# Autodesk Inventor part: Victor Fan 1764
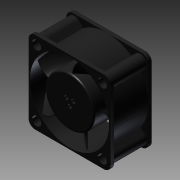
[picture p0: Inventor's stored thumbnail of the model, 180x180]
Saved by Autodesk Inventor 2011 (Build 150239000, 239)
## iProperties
Shininess: 64.0
Length Units: 11272
Angle Units: 11279
Time Units: 11290
Mass Units: 11286
Length Display Precision: 3
Angle Display Precision: 2
Compacted: True
Part Number: Victor Fan 1764
Document SubType Name: Modeling
Created: 2005-12
Designer: Owner
Material: ABS Plastic
Density: 1 g/cm^3
Density: 0.0
Volumn: 0.0
Area: 0.0
PropertySet Name: Model Information
Control State: 0
Master: False
Checked Out: False
Author: Owner
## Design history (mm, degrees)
sketch "Sketch1"
  geometry: L1 (-19.939, 19.939)-(19.939, 19.939); L2 (19.939, 19.939)-(19.939, -19.939); L3 (19.939, -19.939)-(-19.939, -19.939); L4 (-19.939, -19.939)-(-19.939, 19.939); L5 (0, 0)-(0, 19.939); L6 (0, 0)-(0, -19.939); L7 (0, 0)-(19.939, 0); L8 (0, 0)-(-19.939, 0)
  constraints: 16 end point, 4 midpoint, 3 equal length, 3 perpendicular, 2 parallel, 1 horizontal, 1 other
  dimensions: "d0" = 39.878 distance of L1.start L1.end
extrude "Extrusion1" new body sketch "Sketch1" stored distance "d1" = 20.066; taper "d2" = 0 deg
sketch "Sketch2"
  geometry: L1 (19.939, 10.033)-(-19.939, 10.033) reference; L2 (19.939, 10.033)-(19.939, -10.033) reference; L3 (-19.939, -10.033)-(19.939, -10.033) reference; L4 (19.939, 8.331)-(32.639, 8.331); L5 (32.639, 8.331)-(32.639, -8.331); L6 (32.639, -8.331)-(19.939, -8.331); L7 (0, -11.887)-(0, 15.85) reference
  constraints: 6 end point, 2 perpendicular, 2 point on line, 1 parallel
  dimensions: "d3" = 1.7018 distance between parallel lines of L4 L1; "d4" = 12.7 distance of L4.start L4.end; "d5" = 1.7018 distance between parallel lines of L6 L3
revolve "Revolution1" sketch "Sketch2" stored, may be unused: angle "d6" = 90 deg
sketch "Sketch6"
  geometry: L1 (-19.939, 19.939)-(19.939, 19.939) reference; L2 (-19.939, -19.939)-(-19.939, 19.939) reference; L3 (19.939, -19.939)-(-19.939, -19.939) reference; L4 (19.939, 19.939)-(19.939, -19.939) reference; L5 (16.002, 16.002)-(16.002, 19.939); L6 (16.002, 16.002)-(19.939, 16.002); L7 (-16.002, -16.002)-(-19.939, -16.002); L8 (-16.002, -16.002)-(-16.002, -19.939); 2 further points
  constraints: 8 end point, 4 point on line, 3 parallel, 3 perpendicular, 2 horizontal alignment, 2 vertical alignment
  dimensions: "d28" = 32.004 distance of L7.start point (-16.002, 16.002); "d29" = 32.004 distance of L5.start point (-16.002, 16.002)
hole "Hole3" sketch "Sketch6" at (-16.002, 16.002), (16.002, 16.002), (16.002, -16.002), (-16.002, -16.002) diameter "d30" = 4.318; stored, may be unused: countersink angle "d34" = 82 deg, drill point angle "d36" = 118 deg; dims "d31" = 12.7, "d32" = 9.525, "d33" = 6.35, "d35" = 19.05
sketch "Sketch7"
  geometry: L1 (13.721, -1.729)-(11.713, -3.803); L2 (18.283, -6.145)-(16.193, -8.305); C1 r 2.159 at (16.002, -3.937) reference; A1 r 19.939 centre (0, -19.939) between (19.939, -19.939) and (0, 0) reference; A2 r 3.175 centre (16.002, -3.937) between (18.283, -6.145) and (13.721, -1.729)
  constraints: 4 end point, 4 point on circle, 2 tangent, 1 centre point, 1 coincident, 1 parallel
extrude "Extrusion3" join sketch "Sketch7" stored distance "d38" = 19.812; taper "d39" = 0 deg
pattern_circular "Circular Pattern2" dims angle "d42" = 360 deg
fillet "Fillet2" dims "d43" = 3.175
sketch "Sketch8"
  geometry: 1 further point
hole "Hole4" sketch "Sketch8" at (0, 0) diameter "d44" = 38.481; stored, may be unused: countersink angle "d48" = 82 deg, drill point angle "d50" = 118 deg; dims "d45" = 12.7, "d46" = 9.525, "d47" = 6.35, "d49" = 19.05
sketch "Sketch9"
  geometry: L1 (19.939, 16.764)-(19.939, -16.764) reference; L2 (-19.939, -16.764)-(-19.939, 16.764) reference; L3 (10.232, 16.294)-(-3.936, 11.405); L4 (-7.543, -9.416)-(-19.24, -0.045); L5 (-11.131, -4.654)-(-19.158, 1.776); L6 (11.728, 15.253)-(2.006, 11.897); L7 (7.493, -9.456)-(7.493, -17.722); L8 (13.487, -7.924)-(13.487, -13.722); L9 (13.487, -7.924)-(10.847, -5.283); C1 r 2.159 at (16.002, 16.002) reference; A1 r 19.241 centre (0, 0) between (-19.24, -0.045) and (-19.158, 1.776) reference; A2 r 12.065 centre (0, 0) between (-3.936, 11.405) and (-11.131, -4.654); A3 r 12.065 centre (0, 0) between (-7.543, -9.416) and (7.493, -9.456); A4 r 12.065 centre (0, 0) between (10.847, -5.283) and (2.006, 11.897)
  constraints: 14 end point, 12 point on circle, 3 centre point, 3 tangent, 2 parallel, 1 coincident
  dimensions: "d53" = 1.4732 distance between parallel lines of L5 L4; "d54" = 12.446 distance between parallel lines of L1 L7; "d55" = 5.9944 distance between parallel lines of L8 L7; "d58" = 12.065 radius of A2; "d59" = 1.4732 distance between parallel lines of L6 L3; "d60" = 135 deg angle of L8 L9; "d61" = 12.065 radius of A4; "d62" = 12.065 radius of A3
extrude "Extrusion4" join sketch "Sketch9" distance "d63" = 3.81; taper "d64" = 0 deg
sketch "Sketch10"
  geometry: L1 (7.493, -9.456)-(7.493, -17.722) reference; L2 (13.487, -13.722)-(13.487, -7.924) reference; L3 (13.487, -7.924)-(10.847, -5.283) reference; L4 (16.764, -19.939)-(-16.764, -19.939) reference; L5 (-19.939, -16.764)-(-19.939, 16.764) reference; L6 (8.509, -8.553)-(8.509, -18.923); L7 (8.509, -18.923)-(12.471, -18.923); L8 (12.471, -18.923)-(12.471, -8.345); L9 (12.471, -8.345)-(10.341, -6.215); A1 r 19.241 centre (0, 0) between (13.487, -13.722) and (11.728, 15.253) reference; A2 r 12.065 centre (0, 0) between (7.493, -9.456) and (8.509, -8.553)
  constraints: 8 end point, 3 parallel, 3 point on circle, 1 centre point, 1 coincident, 1 perpendicular
  dimensions: "d65" = 1.016 distance between parallel lines of L6 L1; "d66" = 1.016 distance between parallel lines of L4 L7; "d67" = 1.016 distance between parallel lines of L8 L2; "d68" = 1.016 distance between parallel lines of L3 L9
extrude "Extrusion5" cut sketch "Sketch10" distance "d69" = 2.032; taper "d70" = 0 deg
sketch "Sketch11"
  geometry: L1 (16.764, -1.702)-(33.528, -1.702) reference; L2 (33.528, 0)-(0, 0) reference; L3 (26.708, -1.702)-(27.8, -1.702); L4 (27.8, -1.702)-(27.8, 0); L5 (27.8, 0)-(26.708, 0); L6 (26.708, 0)-(26.708, -1.702); L7 (25.273, 0)-(25.273, -1.702) reference; L8 (29.235, 0)-(29.235, -1.702) reference; L9 (26.708, 0)-(25.273, 0); L10 (27.8, 0)-(29.235, 0)
  constraints: 12 end point, 3 collinear, 2 parallel, 2 point on line, 1 horizontal, 1 perpendicular
  dimensions: "d71" = 1.0922 distance between parallel lines of L4 L6
extrude "Extrusion6" cut sketch "Sketch11" distance "d72" = 2.54; taper "d73" = 0 deg
sketch "Sketch12"
  geometry: C1 r 11.938 at (0, 0); A1 r 19.241 centre (0, 0) between (19.24, -0.045) and (19.158, 1.776) reference
  constraints: 1 centre point, 1 coincident, 1 concentric
  dimensions: "d74" = 23.876 diameter of C1
extrude "Extrusion7" join sketch "Sketch12" distance "d75" = 16.256; taper "d76" = 0 deg
fillet "Fillet3" dims "d77" = 0.7874
workplane "Work Plane1"
sketch "Sketch13"
  geometry: L1 (0, 0)-(4, 18.82); L2 (0, 0)-(0, 19.241); L3 (0, 0)-(1.342, 19.194); A1 r 18.669 centre (0, 0) between (3.882, 18.261) and (3.572, 18.324); A2 r 9.196 centre (9.971, 11.37) between (3.882, 18.261) and (0.778, 11.123); A3 r 9.45 centre (9.971, 11.37) between (3.572, 18.324) and (0.523, 11.138); A4 r 11.151 centre (0, 0) between (0.778, 11.123) and (0.523, 11.138); 2 further points
  constraints: 8 point on circle, 6 end point, 4 centre point, 2 coincident, 2 point on line, 1 vertical
  dimensions: "d83" = 4 deg angle of L3 L2; "d84" = 12 deg angle of L1 L2; "d85" = 37.338 diameter of A1; "d86" = 0.254 radial gap between concentric circles of A3 A2
coil "Coil2" sketch "Sketch13" pitch "d99" = 25.4; turns "d101" = 0.15; dims "d100" = 13.97, "d102" = 0, angle "d103" = 90 deg, angle "d104" = 90 deg, "d105" = 0, "d106" = 0
pattern_circular "Circular Pattern4" dims angle "d109" = 360 deg
sketch "Sketch15" dims "d111" = 1.905
  geometry: L1 (0, 0)-(-0.847, 0); L2 (-1.474, 1.076)-(-2.299, 1.552); C1 r 11.151 at (0, 0) reference; C2 r 0.953 at (0.164, -1.762); C3 r 0.953 at (1.803, 1.076)
  constraints: 4 end point, 2 centre point, 1 horizontal, 3 other
  dimensions: "d110" = 1.905 diameter of C3; "d112" = 1.905 diameter of C2; "d114" = 30 deg angle of L1 L2; "d115" = 3.2766 distance of L2.start C2.centre; "d116" = 0 vertical distance of C3.centre L2.start; "d117" = 3.2766 distance of L2.start C3.centre; "d118" = 3.2766 distance of C3.centre C2.centre
extrude "Extrusion8" cut sketch "Sketch15" distance "d119" = 1.905; taper "d120" = 0 deg
body "Solid1"
other parameters: "d37" = 6.35, "d51" = 24.13, "d52" = 1.4732, "d57" = 12.065, "d98" = -0.762
